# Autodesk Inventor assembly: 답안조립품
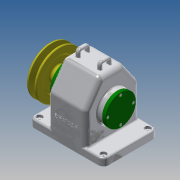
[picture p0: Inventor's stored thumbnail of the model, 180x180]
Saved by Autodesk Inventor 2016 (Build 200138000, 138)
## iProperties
Created: 2016-12
Part Number: 답안조립품
Document SubType Name: Assembly
Designer: Administrator
Author: Administrator
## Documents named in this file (15)
- D:\461207V1002\답안조립품.iam
- D:\461207V1002\본체.ipt
- D:\461207V1002\축.ipt
- D:\461207V1002\뒤커버.ipt
- D:\461207V1002\앞커버.ipt
- D:\461207V1002\스퍼기어.ipt
- D:\461207V1002\키 - 6 x 6 x 22.ipt
- D:\461207V1002\키 - 5 x 5 x 18.ipt
- D:\461207V1002\오일씰 28 40 8.ipt
- D:\461207V1002\베어링 6203.ipt
- D:\461207V1002\볼트 M3 x 8.ipt
- D:\461207V1002\볼트 M3 x 10.ipt
- D:\461207V1002\부시.ipt
- D:\461207V1002\V-벨트풀리.ipt
- D:\461207V1002\멈춤나사 - M4x10.ipt
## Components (9 placed, 3 different names)
1. ISO 4762 M3 x 8:1
2. ISO 4762 M3 x 8:2
3. ISO 4762 M3 x 8:3
4. ISO 4762 M3 x 8:4
5. ISO 4762 M3 x 10:1
6. ISO 4762 M3 x 10:2
7. ISO 4762 M3 x 10:3
8. ISO 4762 M3 x 10:4
9. V-벨트풀리:1
